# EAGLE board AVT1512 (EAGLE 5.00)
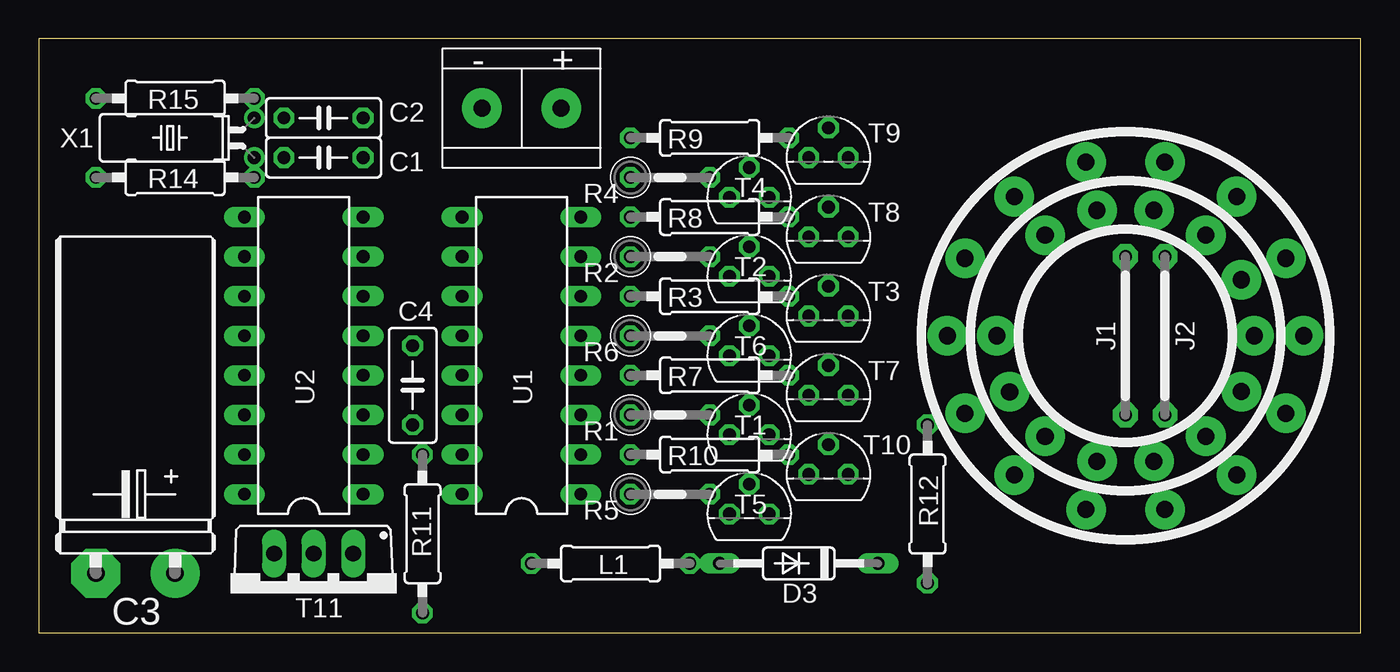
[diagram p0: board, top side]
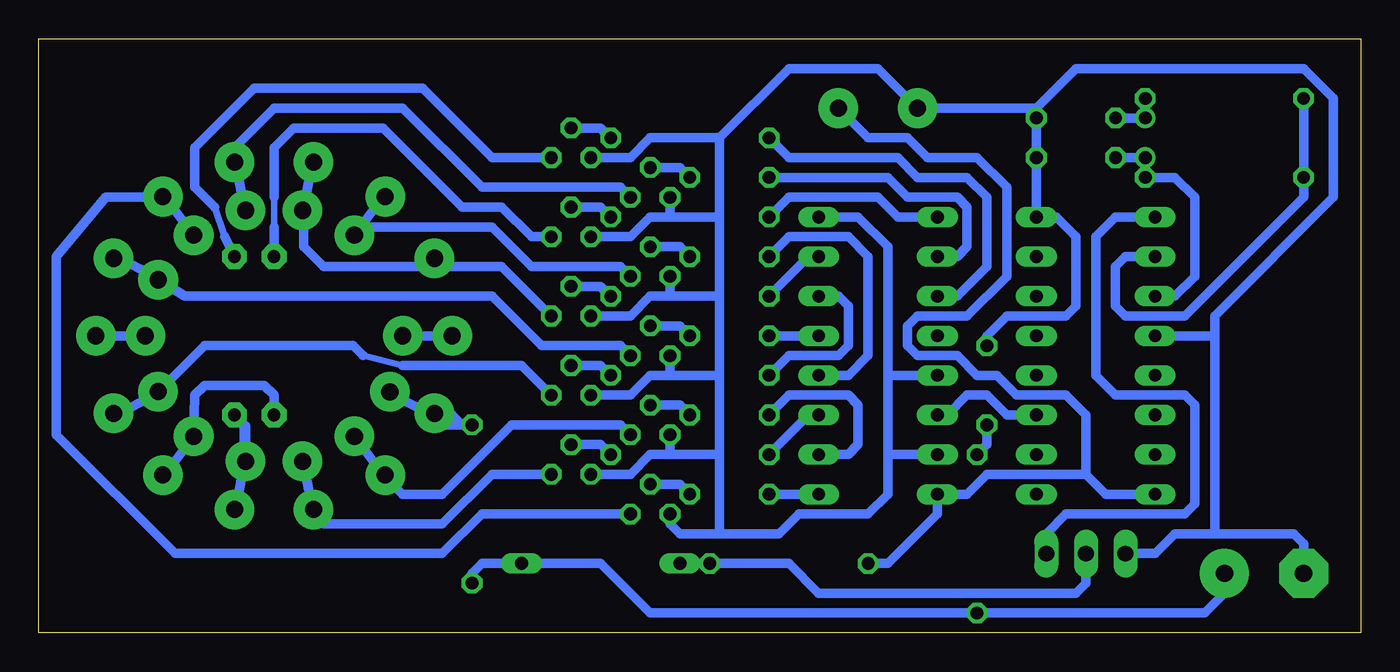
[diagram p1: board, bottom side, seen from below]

Size 84.76 x 38.09 mm. Coordinates in mm from the lower left corner, seen from the top.
Outline: 0,0 84.76,0 84.76,38.09 0,38.09 0,0
Copper layers (1*16): Top 0.035mm / dielectric 1.5mm / Bottom 0.035mm
Design rules "default": minimum track width 10mil, minimum drill 24mil, track to track 8mil, track to pad 8mil, pad to pad 8mil, via to via 8mil, smd to smd 8mil, copper to edge 40mil, drill to drill 8mil, minimum pad ring 10mil, minimum via ring 8mil, stop-mask expansion 4mil, vias tented up to drill 0mil, thermal gap 10mil

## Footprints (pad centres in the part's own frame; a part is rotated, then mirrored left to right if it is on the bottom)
C050-025X075 = drill 0.813 octagon: 1 -2.54,0; 2 2.54,0
E25-10 = drill 1.118 pad 3.15 round: + -11.43,-2.54 | drill 1.118 pad 3.15 octagon: - -11.43,2.54
C050-030X075 = drill 0.813 octagon: 1 -2.54,0; 2 2.54,0
DO35-10 = drill 0.813 long: A 5.08,0; C -5.08,0
30 = drill 1.1 pad 2.54 round: 1 -8.255,0; 2 8.255,0
10 = drill 0.813 pad 1.6 octagon: 1 -5.08,0; 2 5.08,0
20 = drill 1.1 pad 2.54 round: 1 -11.43,0; 2 11.43,0
25 = drill 1.1 pad 2.54 round: 1 -8.255,0; 2 -8.255,0
0207/10 = drill 0.813 pad 1.27 octagon: 1 -5.08,0; 2 5.08,0
0207/5V = drill 0.813 octagon: 1 -2.54,0; 2 2.54,0
TO92 = drill 0.813 octagon: 1 1.27,0; 2 0,1.905; 3 -1.27,0
TO220BV = drill 1.016 long: D 0,-2.54; G -2.54,-2.54; S 2.54,-2.54
DIL16 = drill 0.813 long: 1 -8.89,-3.81; 2 -6.35,-3.81; 3 -3.81,-3.81; 4 -1.27,-3.81; 5 1.27,-3.81; 6 3.81,-3.81; 7 6.35,-3.81; 8 8.89,-3.81; 9 8.89,3.81; 10 6.35,3.81; 11 3.81,3.81; 12 1.27,3.81; 13 -1.27,3.81; 14 -3.81,3.81; 15 -6.35,3.81; 16 -8.89,3.81
ARK2 = drill 1.1 pad 2.54 round: P$1 -2.54,0; P$2 2.54,0
TC38H = drill 0.813 round: 1 -1.27,0; 2 1.27,0

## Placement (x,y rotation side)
C1  [C050-025X075]  18.25,30.48 0 top
C2  [C050-025X075]  18.25,33.02 0 top
C3  [E25-10]  6.19,15.24 90 top
C4  [C050-030X075]  23.96,15.87 90 top
D3  1N4148  [DO35-10]  48.73,4.44 180 top
IC  J30MM  [30]  69.68,19.04 0 top
J1  J10MM  [10]  69.68,19.04 90 top
J2  J10MM  [10]  72.22,19.04 90 top
J11  J20MM  [20]  69.68,19.04 205.8 top
J12  J20MM  [20]  69.68,19.04 77.2 top
J13  J20MM  [20]  69.68,19.04 154.2 top
J14  J20MM  [20]  69.68,19.04 102.8 top
J15  J20MM  [20]  69.68,19.04 128.6 top
J16  J20MM  [20]  69.68,19.04 51.4 top
J17  J20MM  [20]  69.68,19.04 0 top
J18  J30MM  [30]  69.68,19.04 128.6 top
J19  J30MM  [30]  69.68,19.04 102.8 top
J20  J30MM  [30]  69.68,19.04 51.4 top
J22  J25MM  [25]  69.68,19.04 154.3 top
J23  J30MM  [30]  69.68,19.04 77.2 top
J24  J30MM  [30]  69.68,19.04 25.8 top
L1  [0207/10]  36.66,4.44 0 top
R1  [0207/5V]  40.48,13.96 0 top
R2  [0207/5V]  40.48,24.13 0 top
R3  [0207/10]  43.02,21.59 0 top
R4  [0207/5V]  40.48,29.21 0 top
R5  [0207/5V]  40.48,8.89 0 top
R6  [0207/5V]  40.48,19.04 0 top
R7  [0207/10]  43.02,16.5 0 top
R8  [0207/10]  43.02,26.67 0 top
R9  [0207/10]  43.02,31.75 0 top
R10  [0207/10]  43.02,11.43 0 top
R11  [0207/10]  24.6,6.35 270 top
R12  [0207/10]  56.99,8.25 90 top
R14  [0207/10]  8.72,29.21 0 top
R15  [0207/10]  8.72,34.28 0 top
T1  MPSA42  [TO92]  45.55,12.7 0 top
T2  MPSA42  [TO92]  45.55,22.86 0 top
T3  MPSA42  [TO92]  50.63,20.32 0 top
T4  MPSA42  [TO92]  45.55,27.93 0 top
T5  MPSA42  [TO92]  45.55,7.62 0 top
T6  MPSA42  [TO92]  45.55,17.78 0 top
T7  MPSA42  [TO92]  50.63,15.24 0 top
T8  MPSA42  [TO92]  50.63,25.39 0 top
T9  MPSA42  [TO92]  50.63,30.48 0 top
T10  MPSA42  [TO92]  50.63,10.16 0 top
T11  IRF740  [TO220BV]  17.62,2.54 180 top
U1  4017  [DIL16]  30.95,17.78 90 top
U2  4060  [DIL16]  16.98,17.78 90 top
U$2  ARK2  [ARK2]  30.95,33.65 180 top
X1  [TC38H]  13.8,31.75 90 top

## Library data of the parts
C1 C2 C4 L1 R1-R12 R14 R15 = rcl
C3 = !kondensator
D3 = diode
IC J1 J2 J11-J20 J22-J24 = jumper
T1-T10 = transistor-npn
T11 = transistor-power
U1 U2 = 40xx
U$2 = !ark2m
X1 = crystal

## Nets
+9V: L1.1 U1.16 U2.16 U$2.P$1
GND: C1.2 C2.2 C3.- C4.2 T1.3 T2.3 T3.3 T4.3 T5.3 T6.3 T7.3 T8.3 T9.3 T10.3 T11.S U1.8 U1.13 U1.15 U2.8 U2.12 U$2.P$2
N$1: R1.2 T1.2
N$2: R1.1 U1.2
N$3: R2.1 U1.4
N$4: R3.1 U1.7
N$5: R4.1 U1.10
N$6: R5.1 U1.1
N$7: R6.1 U1.5
N$8: R7.1 U1.6
N$9: R8.1 U1.9
N$10: R9.1 U1.11
N$11: R10.1 U1.3
N$12: R10.2 T10.2
N$13: R2.2 T2.2
N$14: R3.2 T3.2
N$15: R4.2 T4.2
N$16: R5.2 T5.2
N$17: R6.2 T6.2
N$18: R7.2 T7.2
N$19: R8.2 T8.2
N$20: R9.2 T9.2
N$21: J24.2 T6.1
N$22: J20.1 T1.1
N$23: J20.2 T5.1
N$24: J23.1 T10.1
N$25: J23.2 T4.1
N$26: J2.1 J19.1
N$27: J18.2 T2.1
N$28: J1.2 T8.1
N$29: J19.2 T3.1
N$30: J1.1 J18.1
N$31: U1.14 U2.3
N$33: J22.1 T7.1
N$34: J2.2 T9.1
N$40: C4.1 R11.1
N$41: T11.G U2.9
N$42: R14.1 R15.1 U2.10
N$43: D3.A L1.2 T11.D
N$45: C3.+ D3.C R11.2 R12.1
N$46: C1.1 R14.2 U2.11 X1.1
N$47: C2.1 R15.2 X1.2

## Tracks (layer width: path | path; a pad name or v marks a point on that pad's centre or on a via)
+9V
  Bottom 0.61: U2.16 16.34,8.89 17.62,10.16 | 17.62,10.16 23.96,10.16 25.23,8.89 U1.16 27.14,7.62 30.32,4.44 L1.1 | U$2.P$1 31.59,31.75 29.05,31.75 27.77,30.48 24.6,30.48 22.7,28.57 22.7,22.86 25.23,20.32 28.41,20.32 29.05,19.68 29.05,18.41 28.41,17.78 25.87,17.78 24.6,16.5 23.33,16.5 22.06,15.24 18.88,15.24 17.62,13.96 17.62,10.16
GND
  Bottom 0.61: 30.32,16.5 30.32,24.76 32.22,26.67 U1.8 | 30.32,16.5 U1.13 | 30.32,11.43 30.32,16.5 | 30.32,11.43 U1.15 | 30.32,11.43 30.32,8.89 31.59,7.62 36.03,7.62 37.3,6.35 41.11,6.35 | 41.11,11.43 44.29,11.43 | 41.11,11.43 41.11,6.35 | 41.11,16.5 44.29,16.5 | 41.11,16.5 41.11,11.43 | 41.11,21.59 44.29,21.59 | 41.11,21.59 41.11,16.5 | 41.11,26.67 44.29,26.67 | 41.11,26.67 41.11,21.59 | 44.29,26.67 T4.3 | 44.29,21.59 T2.3 | 44.29,16.5 T6.3 | 44.29,11.43 T1.3 | T5.3 44.29,6.98 43.65,6.35 41.11,6.35 | T10.3 46.83,10.16 45.55,11.43 44.29,11.43 | T7.3 46.83,15.24 45.55,16.5 44.29,16.5 | T3.3 46.83,20.32 45.55,21.59 44.29,21.59 | T8.3 46.83,25.39 45.55,26.67 44.29,26.67 | T9.3 46.83,30.48 45.55,31.75 41.11,31.75 | 41.11,31.75 41.11,26.67 | T11.S 13.17,5.08 11.9,6.35 9.36,6.35 | 9.36,19.04 9.99,19.04 | 9.36,19.04 9.36,20.32 1.74,27.93 1.74,34.28 3.64,36.19 18.25,36.19 20.79,33.65 | 41.11,31.75 36.66,36.19 30.95,36.19 U$2.P$2 20.79,33.65 | 9.36,6.35 4.28,6.35 3.64,5.71 C3.- | 9.36,19.04 U2.12 | 9.36,6.35 9.36,19.04 | 20.79,33.65 C2.2 C1.2 20.79,28.57 | C4.2 23.96,19.04 22.7,20.32 18.88,20.32 18.25,20.95 18.25,25.39 19.52,26.67 U2.8 20.79,28.57 | 20.79,33.65 20.79,28.57
N$1
  Bottom 0.61: R1.2 43.65,14.6 T1.2
N$2
  Bottom 0.61: U1.2 32.86,11.43 32.22,12.06 32.22,14.6 32.86,15.24 36.66,15.24 R1.1
N$3
  Bottom 0.61: U1.4 32.86,16.5 31.59,17.78 31.59,24.13 32.86,25.39 36.66,25.39 R2.1
N$4
  Bottom 0.61: R3.1 35.4,24.13 U1.7
N$5
  Bottom 0.61: U1.10 25.87,24.13 25.23,24.76 25.23,27.3 25.87,27.93 29.05,27.93 30.32,29.21 R4.1
N$6
  Bottom 0.61: R5.1 U1.1
N$7
  Bottom 0.61: U1.5 R6.1
N$8
  Bottom 0.61: U1.6 33.49,21.59 32.86,20.95 32.86,18.41 33.49,17.78 36.66,17.78 R7.1
N$9
  Bottom 0.61: R8.1 36.66,27.93 30.95,27.93 29.68,26.67 U1.9
N$10
  Bottom 0.61: U1.11 25.87,21.59 23.96,23.49 23.96,27.93 25.23,29.21 28.41,29.21 29.68,30.48 36.66,30.48 R9.1
N$11
  Bottom 0.61: U1.3 35.4,13.96 R10.1
N$12
  Bottom 0.61: R10.2 48.73,12.06 T10.2
N$13
  Bottom 0.61: R2.2 43.65,24.76 T2.2
N$14
  Bottom 0.61: T3.2 48.73,22.22 R3.2
N$15
  Bottom 0.61: R4.2 43.65,29.84 T4.2
N$16
  Bottom 0.61: R5.2 43.65,9.52 T5.2
N$17
  Bottom 0.61: R6.2 43.65,19.68 T6.2
N$18
  Bottom 0.61: T7.2 48.73,17.14 R7.2
N$19
  Bottom 0.61: T8.2 48.73,27.3 R8.2
N$20
  Bottom 0.61: T9.2 48.73,32.38 R9.2
N$21
  Bottom 0.61: T6.1 47.46,18.41 52.54,18.41 55.72,21.59 75.4,21.59 77.12,22.67 | 77.12,22.67 77.3,22.86 79.84,24.13 | 77.12,22.67 J24.2
N$22
  Bottom 0.61: T1.1 47.46,13.33 54.45,13.33 58.89,8.89 61.43,8.89 62.7,10.16 64.53,12.63 | 64.6,12.7 64.53,12.63 | 64.53,12.63 J20.1
N$23
  Bottom 0.61: T5.1 56.35,7.62 58.89,5.08 76.03,5.08 83.66,12.7 83.66,24.13 80.48,27.93 76.67,27.93 74.83,25.46 | 74.77,25.39 74.83,25.46 | 74.83,25.46 J20.2
N$24
  Bottom 0.61: T10.1 55.72,10.16 58.89,6.98 66.51,6.98 67.14,7.62 67.78,10.79 J23.1
N$25
  Bottom 0.61: T4.1 47.46,28.57 56.35,28.57 61.43,33.65 69.68,33.65 72.22,31.11 72.22,30.48 71.59,27.3 71.51,27.22 J23.2
N$26
  Bottom 0.61: J19.1 71.51,13.25 71.59,13.33 | 71.59,13.33 71.59,10.79 72.22,7.62 | 71.59,13.33 J2.1
N$27
  Bottom 0.61: T2.1 47.46,23.49 53.18,23.49 55.72,26.03 63.97,26.03 64.6,25.39 | 64.6,25.39 64.53,25.46 J18.2 | 64.6,25.39 62.7,27.93
N$28
  Bottom 0.406: 69.68,26.03 69.68,27.93
  Bottom 0.61: T8.1 53.18,25.39 55.08,27.3 57.62,27.3 62.7,32.38 68.41,32.38 69.68,31.11 69.68,27.93 | J1.2 69.68,26.03
N$29
  Bottom 0.61: T3.1 55.08,23.49 66.51,23.49 67.78,24.76 67.78,27.3 | 67.78,27.3 67.86,27.22 J19.2 | 67.78,27.3 67.14,30.48
N$30
  Bottom 0.61: J18.1 74.83,12.63 74.77,15.24 74.13,15.87 70.32,15.87 69.68,15.24 J1.1
N$31
  Bottom 0.61: U1.14 26.51,13.96 25.23,15.24 23.96,15.24 22.7,13.96 U2.3
N$33
  Bottom 0.406: 77.12,15.42 77.3,15.24 | 77.12,15.42 J22.1 | 74.13,18.41 77.12,15.42 | 61.43,17.14 63.97,17.78
  Bottom 0.61: 79.84,13.96 77.3,15.24 74.13,18.41 64.6,18.41 63.97,17.78 | T7.1 53.81,17.14 56.99,17.14 61.43,17.14
N$34
  Bottom 0.406: 73.49,27.3 72.86,25.39
  Bottom 0.61: J2.2 72.86,25.39 | 73.49,27.3 74.77,28.57 74.77,31.11 70.95,34.92 60.16,34.92 55.72,30.48 T9.1
N$35
  Bottom 0.61: 76.67,10.16 74.77,12.7
N$36
  Bottom 0.61: 79.21,19.04 79.84,19.04
N$37
  Bottom 0.61: 62.07,15.24 59.52,13.96 | 59.52,13.96 58.89,13.33 58.26,13.33 | 58.26,13.33 57.62,13.33 58.26,13.96 | 58.26,13.96 58.26,13.33 | 58.26,13.33 58.89,13.96 | 58.89,13.96 58.26,13.96 | 58.89,13.96 59.52,13.96
N$38
  Bottom 0.61: 60.79,19.04 60.16,19.04 58.89,19.04
N$39
  Bottom 0.61: 78.57,19.04 80.48,19.04
N$40
  Bottom 0.61: R11.1 23.96,12.06 C4.1
N$41
  Bottom 0.61: 15.71,7.62 11.26,7.62 10.63,8.25 10.63,14.6 11.26,15.24 15.71,15.24 16.98,16.5 16.98,25.39 15.71,26.67 U2.9 | 15.71,7.62 16.34,7.62 | T11.G 20.16,6.35 18.88,7.62 15.71,7.62
N$42
  Bottom 0.61: U2.10 15.08,24.13 15.71,23.49 15.71,20.95 15.08,20.32 11.26,20.32 3.64,27.93 R14.1 | R14.1 R15.1 R14.1
N$43
  Bottom 0.61: D3.A L1.2 36.66,4.44 34.76,2.54 18.25,2.54 17.62,3.17 T11.D
N$45
  Bottom 0.61: R12.1 56.99,3.81 56.35,4.44 D3.C 48.73,4.44 45.55,1.27 R11.2 9.99,1.27 8.72,2.54 C3.+
N$46
  Bottom 0.61: U2.11 11.9,21.59 10.63,22.86 10.63,27.93 11.9,29.21 R14.2 X1.1 C1.1
N$47
  Bottom 0.61: C2.1 X1.2 R15.2

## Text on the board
tPlace: - | +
